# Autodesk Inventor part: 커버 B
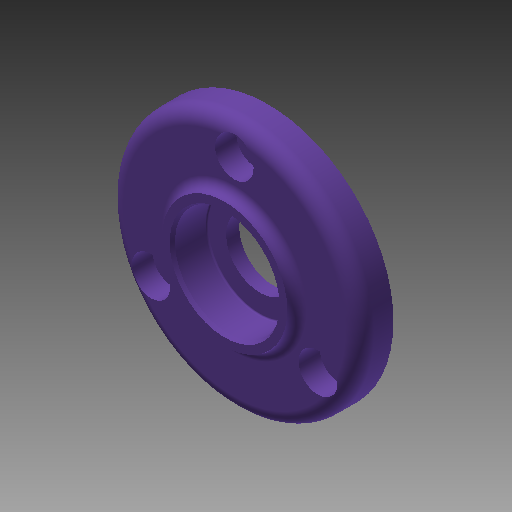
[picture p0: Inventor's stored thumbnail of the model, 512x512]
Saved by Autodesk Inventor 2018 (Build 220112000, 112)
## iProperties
Created: 2020-04
Part Number: 커버 B
Material: 알루미늄 6061
Document SubType Name: Modeling
Designer: mduedu
Density: 2.71 g/cm^3
Mass: 35.0669 g
Surface Area: 63.5386 cm^2
Volume: 12.9398 cm^3
Appearance: 보라색
Author: mduedu
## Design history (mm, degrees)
sketch "스케치1"
  geometry: C1 r 26 at (0, 0); 1 further point
  constraints: 1 centre point, 1 coincident
  dimensions: "d0" = 52 diameter of C1
extrude "돌출1" new body sketch "스케치1" distance "d1" = 7; taper "d2" = 0 deg
sketch "스케치6"
  geometry: C1 r 13 at (0, 0); 1 further point
  constraints: 1 centre point, 1 coincident
  dimensions: "d29" = 26 diameter of C1
extrude "돌출5" join sketch "스케치6" distance "d30" = 2; taper "d31" = 0 deg
fillet "모깎기2" dims "d7" = 3
fillet "모깎기4" dims "d33" = 2
sketch "스케치3" dims "d8" = 40
  geometry: 3 further points
  constraints: 2 vertical alignment, 1 coincident, 2 other
hole "구멍1" sketch "스케치3" at (0, 20) diameter "d9" = 4.5; stored, may be unused: countersink angle "d13" = 90 deg, drill point angle "d15" = 118 deg; dims "d10" = 6, "d11" = 8, "d12" = 4.4, "d14" = 8
sketch "스케치4"
  geometry: C1 r 14 at (0, 0); 1 further point
  constraints: 1 centre point, 1 coincident
  dimensions: "d19" = 28 diameter of C1
extrude "돌출3" join sketch "스케치4" distance "d20" = 4; taper "d21" = 0 deg
sketch "스케치5"
  geometry: C1 r 12 at (0, 0); 1 further point
  constraints: 1 centre point, 1 coincident
  dimensions: "d22" = 24 diameter of C1
extrude "돌출4" cut sketch "스케치5" distance "d23" = 3; taper "d24" = 0 deg
fillet "모깎기3" dims "d25" = 3
chamfer "모따기1" distance "d26" = 0.5; stored, may be unused: second distance "d27" = 2, angle "d28" = 45 deg
sketch "스케치7"
  geometry: 2 further points
  constraints: 1 coincident
hole "구멍2" sketch "스케치7" at (0, 0) diameter "d34" = 14; stored, may be unused: countersink angle "d38" = 90 deg, drill point angle "d40" = 118 deg; dims "d35" = 6, "d36" = 22, "d37" = 7.3, "d39" = 8
fillet "모깎기5" dims "d41" = 0.3
chamfer "모따기2" distance "d42" = 0.7; stored, may be unused: second distance "d43" = 2, angle "d44" = 30 deg
node "솔리드1"
pattern_circular "원형 패턴1" dims angle "d17" = 360 deg
